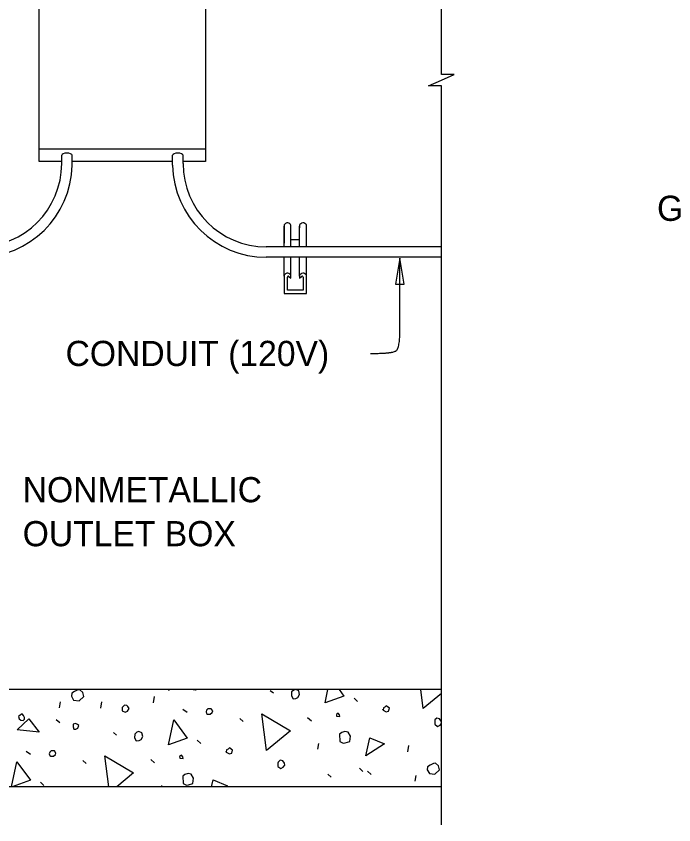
# Model space of a CAD drawing. Extents: x -1660015.2 to -1659984.9, y 2580594.2 to 2580616.7.
# Drawn here: x -1659999.887 to -1659995.935, y 2580605.482 to 2580610.338 of the extents above; entities that cross this region are included whole.
import ezdxf

# ---------------------------------------------------------------- set-up
doc = ezdxf.new("R2010")
doc.units = 0
for name, color, linetype in [('Default', 7, 'Continuous'), ('Miscellaneous', 7, 'Continuous'), ('Miscellaneous3', 7, 'Continuous'), ('PlotBorder_dp', 7, 'Continuous'), ('SheetLines_dp', 7, 'Continuous')]:
    doc.layers.add(name, color=color, linetype=linetype)

msp = doc.modelspace()

# ---------------------------------------------------------------- linework, layer by layer
at = {"layer": 'Default'}
for p, q in [((-1659998.7488, 2580609.5394), (-1659999.7488, 2580609.5394)), ((-1659999.6133, 2580609.453), (-1659999.6133, 2580609.5023)), ((-1659999.5509, 2580609.4424), (-1659999.5509, 2580609.5023)), ((-1659998.9467, 2580609.4424), (-1659998.9467, 2580609.5023)), ((-1659998.8843, 2580609.453), (-1659998.8843, 2580609.5023)), ((-1659998.2359, 2580609.0822), (-1659998.238, 2580609.0861)), ((-1659998.1816, 2580609.0861), (-1659998.1837, 2580609.0822)), ((-1659998.2775, 2580608.9529), (-1659998.2775, 2580609.0779)), ((-1659998.2775, 2580609.0779), (-1659998.2775, 2580608.9753)), ((-1659998.2359, 2580609.0662), (-1659998.2359, 2580609.0822)), ((-1659998.2359, 2580608.9529), (-1659998.2359, 2580609.0779)), ((-1659998.1837, 2580609.0822), (-1659998.1837, 2580609.0662)), ((-1659998.1837, 2580608.9529), (-1659998.1837, 2580609.0779)), ((-1659998.1421, 2580608.9529), (-1659998.1421, 2580609.0779)), ((-1659998.1837, 2580608.9939), (-1659998.2359, 2580608.9939)), ((-1659997.3318, 2580608.9529), (-1659998.3843, 2580608.9529)), ((-1659997.3318, 2580608.8905), (-1659998.3843, 2580608.8905)), ((-1659998.2775, 2580608.7758), (-1659998.2775, 2580608.8905)), ((-1659998.2359, 2580608.7758), (-1659998.2359, 2580608.8905)), ((-1659998.1837, 2580608.7758), (-1659998.1837, 2580608.8905)), ((-1659998.1421, 2580608.7758), (-1659998.1421, 2580608.8905)), ((-1659998.2775, 2580608.7758), (-1659998.2775, 2580608.6732)), ((-1659998.2567, 2580608.6918), (-1659998.2567, 2580608.7715)), ((-1659998.2478, 2580608.7748), (-1659998.2359, 2580608.7641)), ((-1659998.2359, 2580608.7801), (-1659998.238, 2580608.784)), ((-1659998.2359, 2580608.7641), (-1659998.2359, 2580608.7801)), ((-1659998.1816, 2580608.784), (-1659998.1837, 2580608.7801)), ((-1659998.1837, 2580608.7801), (-1659998.1837, 2580608.7641)), ((-1659998.1837, 2580608.7641), (-1659998.1718, 2580608.7748)), ((-1659998.1629, 2580608.7715), (-1659998.1629, 2580608.6918)), ((-1659998.1421, 2580608.6732), (-1659998.1421, 2580608.7758)), ((-1659998.2775, 2580608.6732), (-1659998.1421, 2580608.6732)), ((-1659998.1629, 2580608.6918), (-1659998.2567, 2580608.6918))]:
    msp.add_line(p, q, dxfattribs=at)
for points in [[(-1659999.6133, 2580609.4652), (-1659999.7488, 2580609.4652), (-1659999.7488, 2580612.1902), (-1659998.7488, 2580612.1902), (-1659998.7488, 2580609.4652), (-1659998.8843, 2580609.4652)], [(-1659998.9467, 2580609.4652), (-1659999.5509, 2580609.4652)]]:
    msp.add_lwpolyline(points, dxfattribs=at)
for centre, radius, start, end in [((-1660000.1133, 2580609.453), 0.5, 270, 360), ((-1660000.1133, 2580609.453), 0.5625, 270, 358.9196), ((-1659998.3843, 2580609.453), 0.5625, 181.0804, 270), ((-1659998.3843, 2580609.453), 0.5, 180, 270)]:
    msp.add_arc(centre, radius, start, end, dxfattribs=at)
for centre, major_axis, ratio, start_param, end_param in [((-1659999.5821, 2580609.5023), (-0.0312, 0), 0.446008, 3.14248, 6.283159), ((-1659998.9155, 2580609.5023), (-0.0312, 0), 0.446008, 3.141619, 6.282298), ((-1659998.2567, 2580609.0779), (-0.0208, 0), 0.8951, 3.598509, 6.283184), ((-1659998.1629, 2580609.0779), (0.0208, 0), 0.8951, 0.000002, 2.684677), ((-1659998.2567, 2580608.7758), (-0.0208, 0), 0.8951, 3.598509, 6.283184), ((-1659998.1629, 2580608.7758), (0.0208, 0), 0.8951, 0.000002, 2.684677), ((-1659998.2515, 2580608.7715), (-0.0052, 0), 0.8951, 3.926991, 6.283185), ((-1659998.1681, 2580608.7715), (0.0052, 0), 0.8951, 6.283185, 8.63938)]:
    msp.add_ellipse(centre, major_axis=major_axis, ratio=ratio, start_param=start_param, end_param=end_param, dxfattribs=at)
at = {"layer": 'Miscellaneous'}
for p, q in [((-1659998.9694, 2580606.2894), (-1659998.9685, 2580606.2947)), ((-1659998.3612, 2580606.2893), (-1659998.3415, 2580606.2739)), ((-1659999.6275, 2580606.1855), (-1659999.6214, 2580606.2208)), ((-1659999.3782, 2580606.1824), (-1659999.3728, 2580606.2201)), ((-1659999.061, 2580606.2157), (-1659999.0556, 2580606.2534)), ((-1659997.8571, 2580606.2432), (-1659997.8361, 2580606.2229)), ((-1659998.8851, 2580606.1774), (-1659998.8593, 2580606.1584)), ((-1659998.5439, 2580606.1213), (-1659998.5236, 2580606.1034)), ((-1659998.1365, 2580606.1269), (-1659998.1131, 2580606.1073)), ((-1659999.6475, 2580606.1154), (-1659999.6242, 2580606.0958)), ((-1659999.303, 2580606.0369), (-1659999.2833, 2580606.0215)), ((-1659998.7989, 2580605.9909), (-1659998.7779, 2580605.9706)), ((-1659998.0751, 2580605.9363), (-1659998.069, 2580605.9716)), ((-1659997.5327, 2580605.9212), (-1659997.5273, 2580605.9589)), ((-1659999.8269, 2580605.925), (-1659999.8011, 2580605.9061)), ((-1659999.4857, 2580605.8689), (-1659999.4654, 2580605.8511)), ((-1659999.0783, 2580605.8746), (-1659999.0549, 2580605.855)), ((-1659998.0144, 2580605.7869), (-1659997.9941, 2580605.7691)), ((-1659997.8245, 2580605.8223), (-1659997.8036, 2580605.802)), ((-1659997.7757, 2580605.8043), (-1659997.7548, 2580605.784)), ((-1659999.7407, 2580605.7385), (-1659999.7197, 2580605.7182)), ((-1659997.4903, 2580605.7436), (-1659997.4842, 2580605.7789)), ((-1659999.0121, 2580605.7114), (-1659999.0108, 2580605.7192))]:
    msp.add_line(p, q, dxfattribs=at)
for points in [[(-1659999.5553, 2580606.2541), (-1659999.5416, 2580606.2318), (-1659999.5093, 2580606.2275), (-1659999.4801, 2580606.2535), (-1659999.4865, 2580606.2776), (-1659999.5038, 2580606.2937), (-1659999.5165, 2580606.2929), (-1659999.5369, 2580606.2823), (-1659999.5526, 2580606.2729), (-1659999.5553, 2580606.2541)], [(-1659998.8095, 2580606.2947), (-1659998.807, 2580606.2915), (-1659998.8385, 2580606.2947)], [(-1659998.2319, 2580606.28), (-1659998.2333, 2580606.2563), (-1659998.2233, 2580606.2383), (-1659998.2057, 2580606.2404), (-1659998.1943, 2580606.246), (-1659998.1837, 2580606.2644), (-1659998.1895, 2580606.2861), (-1659998.2073, 2580606.2943), (-1659998.2193, 2580606.2911), (-1659998.2319, 2580606.28)], [(-1659998.0307, 2580606.2148), (-1659998.0137, 2580606.2947)], [(-1659997.9462, 2580606.2947), (-1659997.9173, 2580606.2555), (-1659998.0307, 2580606.2148)], [(-1659997.4419, 2580606.1811), (-1659997.4563, 2580606.2947)], [(-1659997.3318, 2580606.2718), (-1659997.4419, 2580606.1811)], [(-1659999.2497, 2580606.1858), (-1659999.25, 2580606.1676), (-1659999.2323, 2580606.1594), (-1659999.2184, 2580606.1657), (-1659999.2072, 2580606.1817), (-1659999.2152, 2580606.1925), (-1659999.222, 2580606.1984), (-1659999.233, 2580606.2006), (-1659999.2378, 2580606.1994), (-1659999.2497, 2580606.1858)], [(-1659998.7433, 2580606.1507), (-1659998.7372, 2580606.1471), (-1659998.7214, 2580606.1462), (-1659998.7089, 2580606.1573), (-1659998.706, 2580606.1659), (-1659998.7147, 2580606.179), (-1659998.7353, 2580606.1787), (-1659998.7437, 2580606.1713), (-1659998.7459, 2580606.1603), (-1659998.7433, 2580606.1507)], [(-1659997.6824, 2580606.1709), (-1659997.6641, 2580606.1603), (-1659997.6496, 2580606.1642), (-1659997.6445, 2580606.1837), (-1659997.6635, 2580606.1967), (-1659997.6718, 2580606.1893), (-1659997.6808, 2580606.1843), (-1659997.6824, 2580606.1709), (-1659997.6837, 2580606.1758)], [(-1659999.8683, 2580606.1184), (-1659999.8585, 2580606.1107), (-1659999.8451, 2580606.1091), (-1659999.8368, 2580606.1165), (-1659999.8369, 2580606.1268), (-1659999.8426, 2580606.1382), (-1659999.8506, 2580606.149), (-1659999.8638, 2580606.1403), (-1659999.8722, 2580606.1329), (-1659999.8683, 2580606.1184)], [(-1659998.3836, 2580605.9287), (-1659998.4116, 2580606.149), (-1659998.2395, 2580606.0476), (-1659998.3836, 2580605.9287)], [(-1659997.9626, 2580606.1347), (-1659997.9413, 2580606.1326), (-1659997.9439, 2580606.1423), (-1659997.952, 2580606.1531), (-1659997.9628, 2580606.145), (-1659997.9626, 2580606.1347)], [(-1659997.3318, 2580606.0987), (-1659997.3332, 2580606.104), (-1659997.3426, 2580606.1197), (-1659997.359, 2580606.123), (-1659997.3716, 2580606.1119), (-1659997.372, 2580606.104)], [(-1659999.8818, 2580606.0527), (-1659999.8113, 2580606.1181), (-1659999.7487, 2580606.0392), (-1659999.8818, 2580606.0527)], [(-1659999.5449, 2580606.0705), (-1659999.541, 2580606.056), (-1659999.5283, 2580606.0568), (-1659999.5169, 2580606.0625), (-1659999.5111, 2580606.0795), (-1659999.5179, 2580606.0855), (-1659999.5295, 2580606.0901), (-1659999.544, 2580606.0863), (-1659999.5449, 2580606.0705)], [(-1659998.9724, 2580605.9625), (-1659998.9404, 2580606.1134), (-1659998.8591, 2580606.0032), (-1659998.9724, 2580605.9625)], [(-1659997.372, 2580606.104), (-1659997.3723, 2580606.0858), (-1659997.3557, 2580606.0721), (-1659997.3401, 2580606.0815), (-1659997.3318, 2580606.0901)], [(-1659999.1737, 2580606.0276), (-1659999.1751, 2580606.0039), (-1659999.1651, 2580605.9859), (-1659999.1475, 2580605.988), (-1659999.1361, 2580605.9937), (-1659999.1255, 2580606.012), (-1659999.1313, 2580606.0338), (-1659999.149, 2580606.042), (-1659999.1611, 2580606.0387), (-1659999.1737, 2580606.0276)], [(-1659997.9438, 2580606.0259), (-1659997.9425, 2580605.9822), (-1659997.9217, 2580605.9723), (-1659997.9096, 2580605.9755), (-1659997.883, 2580605.9826), (-1659997.8787, 2580606.0148), (-1659997.8931, 2580606.0394), (-1659997.9119, 2580606.0422), (-1659997.9312, 2580606.037), (-1659997.9438, 2580606.0259)], [(-1659997.7852, 2580605.8975), (-1659997.7621, 2580606.0047), (-1659997.6748, 2580605.9685), (-1659997.7852, 2580605.8975)], [(-1659999.6851, 2580605.8983), (-1659999.679, 2580605.8948), (-1659999.6632, 2580605.8938), (-1659999.6507, 2580605.905), (-1659999.6478, 2580605.9135), (-1659999.6565, 2580605.9267), (-1659999.6771, 2580605.9264), (-1659999.6855, 2580605.9189), (-1659999.6877, 2580605.908), (-1659999.6851, 2580605.8983)], [(-1659998.6242, 2580605.9186), (-1659998.6058, 2580605.908), (-1659998.5914, 2580605.9119), (-1659998.5862, 2580605.9314), (-1659998.6052, 2580605.9444), (-1659998.6136, 2580605.937), (-1659998.6226, 2580605.932), (-1659998.6242, 2580605.9186), (-1659998.6255, 2580605.9234)], [(-1659999.3299, 2580605.7114), (-1659999.3534, 2580605.8966), (-1659999.1813, 2580605.7952), (-1659999.2829, 2580605.7114)], [(-1659998.9044, 2580605.8823), (-1659998.8831, 2580605.8803), (-1659998.8857, 2580605.8899), (-1659998.8938, 2580605.9007), (-1659998.9046, 2580605.8927), (-1659998.9044, 2580605.8823)], [(-1659999.9139, 2580605.7114), (-1659999.8822, 2580605.861), (-1659999.8009, 2580605.7508), (-1659999.9106, 2580605.7114)], [(-1659998.3138, 2580605.8517), (-1659998.3141, 2580605.8335), (-1659998.2975, 2580605.8198), (-1659998.2819, 2580605.8291), (-1659998.2718, 2580605.8396), (-1659998.275, 2580605.8517), (-1659998.2844, 2580605.8673), (-1659998.3008, 2580605.8707), (-1659998.3133, 2580605.8595), (-1659998.3138, 2580605.8517)], [(-1659997.4181, 2580605.8121), (-1659997.4044, 2580605.7899), (-1659997.3721, 2580605.7856), (-1659997.3429, 2580605.8116), (-1659997.3493, 2580605.8357), (-1659997.3666, 2580605.8518), (-1659997.3793, 2580605.851), (-1659997.3997, 2580605.8403), (-1659997.4154, 2580605.831), (-1659997.4181, 2580605.8121)], [(-1659998.8856, 2580605.7735), (-1659998.8842, 2580605.7299), (-1659998.8634, 2580605.7199), (-1659998.8514, 2580605.7231), (-1659998.8248, 2580605.7303), (-1659998.8205, 2580605.7625), (-1659998.8349, 2580605.7871), (-1659998.8537, 2580605.7898), (-1659998.873, 2580605.7846), (-1659998.8856, 2580605.7735)], [(-1659998.7127, 2580605.7114), (-1659998.7039, 2580605.7523), (-1659998.6166, 2580605.7162), (-1659998.624, 2580605.7114)]]:
    msp.add_lwpolyline(points, dxfattribs=at)
at = {"layer": 'Miscellaneous3'}
for p, q in [((-1659997.3318, 2580606.2947), (-1660002.3746, 2580606.2947)), ((-1659997.3318, 2580605.7114), (-1660002.3746, 2580605.7114))]:
    msp.add_line(p, q, dxfattribs=at)
at = {"layer": 'SheetLines_dp'}
msp.add_lwpolyline([(-1659997.3318, 2580605.4823), (-1659997.3318, 2580609.9205), (-1659997.4093, 2580609.9205), (-1659997.3318, 2580609.9542), (-1659997.2543, 2580609.988), (-1659997.3318, 2580609.988), (-1659997.3318, 2580611.0927)], dxfattribs=at)
msp.add_lwpolyline([(-1659997.5812, 2580608.8854), (-1659997.6077, 2580608.7292), (-1659997.5547, 2580608.7292)], close=True, dxfattribs=at)
msp.add_open_spline([(-1659997.7572, 2580608.3127), (-1659997.6308, 2580608.3127), (-1659997.5812, 2580608.3424), (-1659997.5812, 2580608.568), (-1659997.5812, 2580608.8854)], degree=2, dxfattribs=at)

# ---------------------------------------------------------------- texts
at = {"layer": 'PlotBorder_dp'}
for s, p in [('GROUT AFTER INSTALLATION', (-1659996.0365, 2580609.1088)), ('CONDUIT (120V)', (-1659999.5901, 2580608.2372)), ('NONMETALLIC ', (-1659999.8477, 2580607.4191)), ('OUTLET BOX', (-1659999.8477, 2580607.1551))]:
    msp.add_text(s, height=0.1512, dxfattribs=at).set_placement(p)

doc.saveas('drawing.dxf')
